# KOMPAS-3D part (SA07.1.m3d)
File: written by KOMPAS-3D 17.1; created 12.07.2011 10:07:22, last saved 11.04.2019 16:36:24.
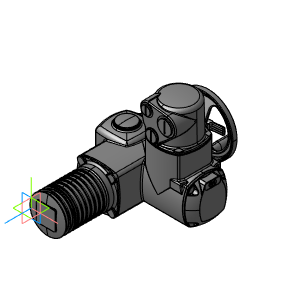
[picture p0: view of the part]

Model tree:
1. Плоскость XY
2. Плоскость ZX
3. Плоскость ZY
4. Ось X
5. Ось Y
6. Ось Z
7. Начало координат
8. Операция без истории:2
